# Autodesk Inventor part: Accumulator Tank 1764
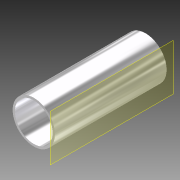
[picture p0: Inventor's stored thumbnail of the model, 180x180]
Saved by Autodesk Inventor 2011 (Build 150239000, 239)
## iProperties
Created: 2010-01
Part Number: Accumulator Tank 1764
Document SubType Name: Modeling
Designer: cmcfadden
Density: 1 g/cm^3
Author: cmcfadden
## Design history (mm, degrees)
sketch "Sketch1"
  geometry: C1 r 26.416 at (10.426, -13.014); 1 further point
  constraints: 1 centre point
  dimensions: "d0" = 52.832 diameter of C1
extrude "Extrusion1" new body sketch "Sketch1" distance "d1" = 139.7508; taper "d2" = 0 deg
workplane "Work Plane1"
sketch "Sketch2"
  geometry: 1 further point
sketch "Sketch3"
  geometry: C1 r 26.416 at (0, 0) reference; C2 r 23.647 at (0, 0); 1 further point
  constraints: 1 centre point, 1 coincident
  dimensions: "d14" = 47.2948 diameter of C2
extrude "Extrusion2" cut sketch "Sketch3" stored distance "d15" = 25.4; taper "d16" = 0 deg
body "Solid1"
other parameters: "d3" = 38.1
